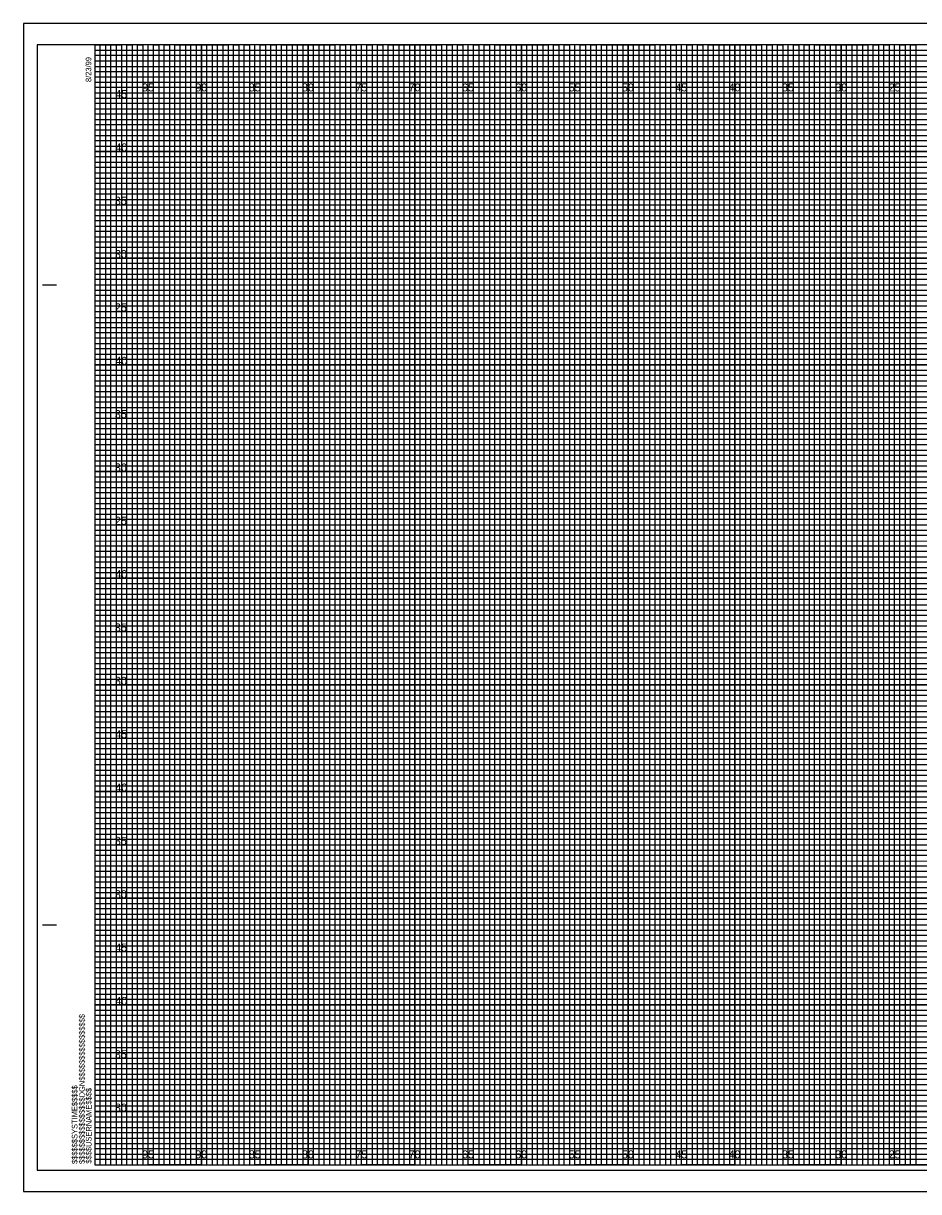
# Model space of a CAD drawing. Extents: x -7 to 162, y 107 to 217.
# Drawn here: x -6.7 to 77.2, y 107.5 to 217 of the extents above; entities that cross this region are included whole.
import ezdxf

# ---------------------------------------------------------------- set-up
doc = ezdxf.new("R2010")
doc.units = 0
for name, color, linetype in [('Exist Cross Section Cell', 7, 'Continuous'), ('Exist XS Center Line Elevation Label', 7, 'Continuous'), ('Exist XS Ground Line', 7, 'Continuous'), ('Prop CMT Pvmt Course 1', 7, 'Continuous'), ('Prop CMT Pvmt Course 2', 7, 'Continuous'), ('Prop CMT Pvmt Course 3', 7, 'Continuous'), ('Prop CMT Shld Paved Course 1', 7, 'Continuous'), ('Prop CMT Shld Paved Course 3', 7, 'Continuous'), ('Prop CMT Slope Grass', 7, 'Continuous'), ('Prop CMT Subgrade Earthwork', 7, 'Continuous'), ('Scratch_Level_0', 7, 'Continuous')]:
    doc.layers.add(name, color=color, linetype=linetype)

msp = doc.modelspace()

# ---------------------------------------------------------------- linework, layer by layer
at = {"layer": 'Exist XS Center Line Elevation Label'}
for points in [[(0, 215), (2.5, 215), (2.5, 110), (7.5, 110), (7.5, 215), (12.5, 215), (12.5, 110), (17.5, 110), (17.5, 215), (22.5, 215), (22.5, 110), (27.5, 110), (27.5, 215), (32.5, 215), (32.5, 110), (37.5, 110), (37.5, 215), (42.5, 215), (42.5, 110), (47.5, 110), (47.5, 215), (52.5, 215), (52.5, 110), (57.5, 110), (57.5, 215), (62.5, 215), (62.5, 110), (67.5, 110), (67.5, 215), (72.5, 215), (72.5, 110), (77.5, 110)], [(0, 212.5), (137.5, 212.5)], [(0, 202.5), (160, 202.5), (160, 207.5), (0, 207.5)], [(0, 192.5), (160, 192.5), (160, 197.5), (0, 197.5)], [(0, 182.5), (160, 182.5), (160, 187.5), (0, 187.5)], [(0, 172.5), (160, 172.5), (160, 177.5), (0, 177.5)], [(0, 162.5), (160, 162.5), (160, 167.5), (0, 167.5)], [(0, 152.5), (160, 152.5), (160, 157.5), (0, 157.5)], [(0, 142.5), (160, 142.5), (160, 147.5), (0, 147.5)], [(0, 132.5), (160, 132.5), (160, 137.5), (0, 137.5)], [(0, 122.5), (160, 122.5), (160, 127.5), (0, 127.5)], [(0, 112.5), (160, 112.5), (160, 117.5), (0, 117.5)]]:
    msp.add_lwpolyline(points, dxfattribs=at)
at = {"layer": 'Exist XS Ground Line'}
for p, q in [((5, 215), (0, 215)), ((5, 110), (5, 215)), ((15, 215), (10, 215)), ((10, 215), (10, 110)), ((15, 110), (15, 215)), ((25, 215), (20, 215)), ((20, 215), (20, 110)), ((25, 110), (25, 215)), ((35, 215), (30, 215)), ((30, 215), (30, 110)), ((35, 110), (35, 215)), ((45, 215), (40, 215)), ((40, 215), (40, 110)), ((45, 110), (45, 215)), ((55, 215), (50, 215)), ((50, 215), (50, 110)), ((55, 110), (55, 215)), ((65, 215), (60, 215)), ((60, 215), (60, 110)), ((65, 110), (65, 215)), ((75, 215), (70, 215)), ((70, 215), (70, 110)), ((75, 110), (75, 215)), ((10, 110), (5, 110)), ((20, 110), (15, 110)), ((30, 110), (25, 110)), ((40, 110), (35, 110)), ((50, 110), (45, 110)), ((60, 110), (55, 110)), ((70, 110), (65, 110)), ((80, 110), (75, 110))]:
    msp.add_line(p, q, dxfattribs=at)
for points in [[(0, 210), (160, 210), (160, 205), (0, 205)], [(0, 200), (160, 200), (160, 195), (0, 195)], [(0, 190), (160, 190), (160, 185), (0, 185)], [(0, 180), (160, 180), (160, 175), (0, 175)], [(0, 170), (160, 170), (160, 165), (0, 165)], [(0, 160), (160, 160), (160, 155), (0, 155)], [(0, 150), (160, 150), (160, 145), (0, 145)], [(0, 140), (160, 140), (160, 135), (0, 135)], [(0, 130), (160, 130), (160, 125), (0, 125)], [(0, 120), (160, 120), (160, 115), (0, 115)]]:
    msp.add_lwpolyline(points, dxfattribs=at)
at = {"layer": 'Prop CMT Pvmt Course 1'}
msp.add_lwpolyline([(-5.4, 109.5), (161.2, 109.5), (161.2, 215), (-5.4, 215)], close=True, dxfattribs=at)
at = {"layer": 'Prop CMT Pvmt Course 2'}
for p, q in [((5, 110), (5, 215)), ((10, 110), (10, 215)), ((15, 110), (15, 215)), ((20, 110), (20, 215)), ((25, 110), (25, 215)), ((30, 110), (30, 215)), ((35, 110), (35, 215)), ((40, 110), (40, 215)), ((45, 110), (45, 215)), ((50, 110), (50, 215)), ((55, 110), (55, 215)), ((60, 110), (60, 215)), ((65, 110), (65, 215)), ((70, 110), (70, 215)), ((75, 110), (75, 215)), ((0, 210), (160, 210)), ((0, 205), (160, 205)), ((0, 200), (160, 200)), ((0, 195), (160, 195)), ((0, 190), (160, 190)), ((0, 185), (160, 185)), ((0, 180), (160, 180)), ((0, 175), (160, 175)), ((0, 170), (160, 170)), ((0, 165), (160, 165)), ((0, 160), (160, 160)), ((0, 155), (160, 155)), ((0, 150), (160, 150)), ((0, 145), (160, 145)), ((0, 140), (160, 140)), ((0, 135), (160, 135)), ((0, 130), (160, 130)), ((0, 125), (160, 125)), ((0, 120), (160, 120)), ((0, 115), (160, 115))]:
    msp.add_line(p, q, dxfattribs=at)
at = {"layer": 'Prop CMT Pvmt Course 3'}
for p, q in [((161.65, 217), (-6.7, 217)), ((-6.7, 217), (-6.7, 107.5)), ((-6.7, 107.5), (161.65, 107.5))]:
    msp.add_line(p, q, dxfattribs=at)
at = {"layer": 'Prop CMT Shld Paved Course 1'}
for points in [[(0, 110), (0.5, 110), (0.5, 215), (1, 215), (1, 110)], [(1, 110), (1.5, 110), (1.5, 215), (2, 215), (2, 110)], [(2.5, 110), (3, 110), (3, 215), (3.5, 215), (3.5, 110)], [(3.5, 110), (4, 110), (4, 215), (4.5, 215), (4.5, 110)], [(5, 110), (5.5, 110), (5.5, 215), (6, 215), (6, 110)], [(6, 110), (6.5, 110), (6.5, 215), (7, 215), (7, 110)], [(7.5, 110), (8, 110), (8, 215), (8.5, 215), (8.5, 110)], [(8.5, 110), (9, 110), (9, 215), (9.5, 215), (9.5, 110)], [(10, 110), (10.5, 110), (10.5, 215), (11, 215), (11, 110)], [(11, 110), (11.5, 110), (11.5, 215), (12, 215), (12, 110)], [(12.5, 110), (13, 110), (13, 215), (13.5, 215), (13.5, 110)], [(13.5, 110), (14, 110), (14, 215), (14.5, 215), (14.5, 110)], [(15, 110), (15.5, 110), (15.5, 215), (16, 215), (16, 110)], [(16, 110), (16.5, 110), (16.5, 215), (17, 215), (17, 110)], [(17.5, 110), (18, 110), (18, 215), (18.5, 215), (18.5, 110)], [(18.5, 110), (19, 110), (19, 215), (19.5, 215), (19.5, 110)], [(20, 110), (20.5, 110), (20.5, 215), (21, 215), (21, 110)], [(21, 110), (21.5, 110), (21.5, 215), (22, 215), (22, 110)], [(22.5, 110), (23, 110), (23, 215), (23.5, 215), (23.5, 110)], [(23.5, 110), (24, 110), (24, 215), (24.5, 215), (24.5, 110)], [(25, 110), (25.5, 110), (25.5, 215), (26, 215), (26, 110)], [(26, 110), (26.5, 110), (26.5, 215), (27, 215), (27, 110)], [(27.5, 110), (28, 110), (28, 215), (28.5, 215), (28.5, 110)], [(28.5, 110), (29, 110), (29, 215), (29.5, 215), (29.5, 110)], [(30, 110), (30.5, 110), (30.5, 215), (31, 215), (31, 110)], [(31, 110), (31.5, 110), (31.5, 215), (32, 215), (32, 110)], [(32.5, 110), (33, 110), (33, 215), (33.5, 215), (33.5, 110)], [(33.5, 110), (34, 110), (34, 215), (34.5, 215), (34.5, 110)], [(35, 110), (35.5, 110), (35.5, 215), (36, 215), (36, 110)], [(36, 110), (36.5, 110), (36.5, 215), (37, 215), (37, 110)], [(37.5, 110), (38, 110), (38, 215), (38.5, 215), (38.5, 110)], [(38.5, 110), (39, 110), (39, 215), (39.5, 215), (39.5, 110)], [(40, 110), (40.5, 110), (40.5, 215), (41, 215), (41, 110)], [(41, 110), (41.5, 110), (41.5, 215), (42, 215), (42, 110)], [(42.5, 110), (43, 110), (43, 215), (43.5, 215), (43.5, 110)], [(43.5, 110), (44, 110), (44, 215), (44.5, 215), (44.5, 110)], [(45, 110), (45.5, 110), (45.5, 215), (46, 215), (46, 110)], [(46, 110), (46.5, 110), (46.5, 215), (47, 215), (47, 110)], [(47.5, 110), (48, 110), (48, 215), (48.5, 215), (48.5, 110)], [(48.5, 110), (49, 110), (49, 215), (49.5, 215), (49.5, 110)], [(50, 110), (50.5, 110), (50.5, 215), (51, 215), (51, 110)], [(51, 110), (51.5, 110), (51.5, 215), (52, 215), (52, 110)], [(52.5, 110), (53, 110), (53, 215), (53.5, 215), (53.5, 110)], [(53.5, 110), (54, 110), (54, 215), (54.5, 215), (54.5, 110)], [(55, 110), (55.5, 110), (55.5, 215), (56, 215), (56, 110)], [(56, 110), (56.5, 110), (56.5, 215), (57, 215), (57, 110)], [(57.5, 110), (58, 110), (58, 215), (58.5, 215), (58.5, 110)], [(58.5, 110), (59, 110), (59, 215), (59.5, 215), (59.5, 110)], [(60, 110), (60.5, 110), (60.5, 215), (61, 215), (61, 110)], [(61, 110), (61.5, 110), (61.5, 215), (62, 215), (62, 110)], [(62.5, 110), (63, 110), (63, 215), (63.5, 215), (63.5, 110)], [(63.5, 110), (64, 110), (64, 215), (64.5, 215), (64.5, 110)], [(65, 110), (65.5, 110), (65.5, 215), (66, 215), (66, 110)], [(66, 110), (66.5, 110), (66.5, 215), (67, 215), (67, 110)], [(67.5, 110), (68, 110), (68, 215), (68.5, 215), (68.5, 110)], [(68.5, 110), (69, 110), (69, 215), (69.5, 215), (69.5, 110)], [(70, 110), (70.5, 110), (70.5, 215), (71, 215), (71, 110)], [(71, 110), (71.5, 110), (71.5, 215), (72, 215), (72, 110)], [(72.5, 110), (73, 110), (73, 215), (73.5, 215), (73.5, 110)], [(73.5, 110), (74, 110), (74, 215), (74.5, 215), (74.5, 110)], [(75, 110), (75.5, 110), (75.5, 215), (76, 215), (76, 110)], [(76, 110), (76.5, 110), (76.5, 215), (77, 215), (77, 110)]]:
    msp.add_lwpolyline(points, dxfattribs=at)
at = {"layer": 'Prop CMT Shld Paved Course 3'}
msp.add_lwpolyline([(-6.7, 107.5), (161.65, 107.5), (161.65, 217), (-6.7, 217)], close=True, dxfattribs=at)
at = {"layer": 'Prop CMT Slope Grass'}
for p, q in [((-4.9, 192.5), (-3.65, 192.5)), ((-4.85, 192.5), (-3.6, 192.5)), ((-4.9, 132.5), (-3.65, 132.5)), ((-4.85, 132.5), (-3.6, 132.5)), ((0, 110), (0, 110)), ((0, 110), (0, 110)), ((0, 110), (0, 110)), ((0, 110), (0, 110)), ((0, 110), (0, 110)), ((0, 110), (0, 110)), ((0, 110), (0, 110))]:
    msp.add_line(p, q, dxfattribs=at)
msp.add_lwpolyline([(160, 215), (0, 215), (0, 110), (160, 110)], close=True, dxfattribs=at)
at = {"layer": 'Scratch_Level_0'}
for p, q in [((0, 214.5), (130, 214.5)), ((130, 213.99), (0, 213.99)), ((0, 213.99), (0, 213.5)), ((0, 213.5), (130, 213.5)), ((130, 212.94), (0, 212.94)), ((0, 212.94), (0, 212)), ((0, 212), (160, 212))]:
    msp.add_line(p, q, dxfattribs=at)
for points in [[(0, 211.5), (135, 211.5), (160, 211.5), (160, 211), (0, 211)], [(0, 210.5), (160, 210.5), (160, 209.5), (0, 209.5)], [(0, 209), (160, 209), (160, 208.5), (0, 208.49)], [(0, 208), (160, 208), (160, 207), (0, 207)], [(0, 206.5), (160, 206.5), (160, 206), (0, 206)], [(0, 205.5), (160, 205.5), (160, 204.5), (0, 204.5)], [(0, 204), (160, 204), (160, 203.5), (0, 203.5)], [(0, 203), (160, 203), (160, 202), (0, 202)], [(0, 201.5), (160, 201.5), (160, 201), (0, 201)], [(0, 200.5), (160, 200.5), (160, 199.5), (0, 199.5)], [(0, 199), (160, 199), (160, 198.5), (0, 198.5)], [(0, 198), (160, 198), (160, 196.97), (160, 196.5), (160, 196), (0, 196)], [(0, 197), (160, 197), (160, 196.5), (0, 196.5)], [(0, 195.5), (160, 195.5), (160, 194.5), (0, 194.52)], [(0, 194.52), (160, 194.5), (160, 194), (0, 194)], [(0, 193.5), (160, 193.5), (160, 193), (0, 193)], [(0, 192), (160, 192), (160, 191.5), (0, 191.5)], [(0, 191), (160, 191), (160, 190.5), (0, 190.5)], [(-0.04, 189.44), (160, 189.44), (160, 188.94), (-0.04, 188.94)], [(0, 188.5), (160, 188.5), (160, 188), (0, 188)], [(0, 187), (160, 187), (160, 186.5), (0, 186.5)], [(0, 186), (160, 186), (160, 185.5), (0, 185.5)], [(0, 184.5), (160, 184.5), (160, 184), (0, 184)], [(0, 183.5), (160, 183.5), (160, 183), (0, 183)], [(0, 182), (160, 182), (160, 181.5), (0, 181.5)], [(0, 181), (160, 181), (160, 180.5), (0, 180.5)], [(0, 179.5), (160, 179.5), (160, 178.99), (0, 179)], [(0, 178.5), (160, 178.5), (160, 178), (0, 178)], [(0, 177), (160, 177), (160, 176.5), (0, 176.5)], [(0, 176), (160, 176), (160, 175.5), (0, 175.5)], [(0, 174.5), (160, 174.5), (160, 174), (0, 174)], [(0, 173.5), (160, 173.5), (160, 173), (0, 173)], [(0, 172), (160, 172), (160, 171.5), (0, 171.5)], [(0, 171), (160, 171), (160, 170.5), (0, 170.5)], [(0, 169.5), (160, 169.5), (160, 169), (0, 169)], [(0, 168.5), (160.03, 168.46), (160, 168), (0, 168)], [(0, 167), (160, 167), (160, 166.5), (0, 166.5)], [(0, 166), (160, 166), (160, 165.5), (0, 165.5)], [(0, 164.5), (160, 164.5), (160, 164), (0, 164)], [(0, 163.5), (160, 163.5), (160, 163), (0, 163)], [(0, 162), (160, 162), (160, 161.5), (0, 161.5)], [(0, 161), (160, 161), (160, 160.5), (0, 160.5)], [(0, 159.5), (160, 159.5), (160, 159), (0, 159)], [(0, 158.5), (160, 158.5), (160, 158), (0, 158)], [(0, 157), (160, 157), (160, 156.5), (0, 156.5)], [(0, 156), (160, 156), (160, 155.5), (0, 155.5)], [(0, 154.5), (160, 154.5), (160, 154), (0, 154)], [(0, 153.5), (160, 153.5), (160, 153), (0, 153)], [(0, 152), (160, 152), (160, 151.5), (0, 151.5)], [(0, 151), (160, 151), (160, 150.5), (0, 150.5)], [(0, 149.5), (160, 149.5), (160, 148.99), (0, 149)], [(0, 148.5), (160, 148.5), (160, 148), (0, 148)], [(0, 147), (160, 147), (160, 146.5), (0, 146.5)], [(0, 146), (160, 146), (160, 145.5), (0, 145.5)], [(0, 144.5), (160, 144.5), (160, 144), (0, 144)], [(0, 143.5), (160, 143.5), (160, 143), (0, 143)], [(0, 142), (160, 142), (160, 141.5), (0, 141.5)], [(0, 141), (160, 141), (160, 140.5), (0, 140.5)], [(0, 139.5), (160, 139.5), (160, 139), (0, 139)], [(0, 138.5), (160.03, 138.46), (160, 138), (0, 138)], [(0, 137), (160, 137), (160, 136.5), (0, 136.5)], [(0, 136), (160, 136), (160, 135.5), (0, 135.5)], [(0, 134.5), (160, 134.5), (160, 134), (0, 134)], [(0, 133.5), (160, 133.5), (160, 133), (0, 133)], [(0, 132), (160, 132), (160, 131.5), (0, 131.5)], [(0, 131), (160, 131), (160, 130.5), (0, 130.5)], [(0, 129.5), (160, 129.5), (160, 129), (0, 129)], [(0, 128.5), (160, 128.5), (160, 128), (0, 128)], [(0, 127), (160, 127), (160, 126.5), (0, 126.5)], [(0, 126), (160, 126), (160, 125.5), (0, 125.5)], [(0, 124.5), (160, 124.5), (160, 124), (0, 124)], [(0, 123.5), (160, 123.5), (160, 123), (0, 123)], [(0, 122), (160, 122), (160, 121.5), (0, 121.5)], [(0, 121), (160, 121), (160, 120.5), (0, 120.5)], [(0, 119.5), (160, 119.5), (160, 119), (0, 119)], [(0, 118.5), (160, 118.5), (160, 118), (0, 118)], [(0, 117), (160, 117), (160, 116.5), (0, 116.5)], [(0, 116), (160, 116), (160, 115.5), (0, 115.5)], [(0, 114.5), (160, 114.5), (160, 114), (0, 114)], [(0, 113.5), (160, 113.5), (160, 113), (0, 113)], [(0, 112), (160, 112), (160, 111.5), (0, 111.5)], [(0, 111), (160, 111), (160, 110.5), (0, 110.5)]]:
    msp.add_lwpolyline(points, dxfattribs=at)

# ---------------------------------------------------------------- texts
at = {"layer": 'Exist Cross Section Cell'}
for s, p in [('95', (4.44, 210.62)), ('90', (9.43, 210.62)), ('85', (14.44, 210.62)), ('80', (19.43, 210.62)), ('75', (24.44, 210.62)), ('70', (29.43, 210.62)), ('65', (34.44, 210.62)), ('60', (39.43, 210.62)), ('55', (44.44, 210.62)), ('50', (49.43, 210.62)), ('45', (54.44, 210.62)), ('40', (59.43, 210.62)), ('35', (64.44, 210.62)), ('30', (69.43, 210.62)), ('25', (74.44, 210.62)), ('95', (4.44, 110.62)), ('90', (9.43, 110.62)), ('85', (14.44, 110.62)), ('80', (19.43, 110.62)), ('75', (24.44, 110.62)), ('70', (29.43, 110.62)), ('65', (34.44, 110.62)), ('60', (39.43, 110.62)), ('55', (44.44, 110.62)), ('50', (49.43, 110.62)), ('45', (54.44, 110.62)), ('40', (59.43, 110.62)), ('35', (64.44, 110.62)), ('30', (69.43, 110.62)), ('25', (74.44, 110.62))]:
    msp.add_text(s, height=0.75, dxfattribs=at).set_placement(p)
at = {"layer": 'Prop CMT Slope Grass'}
for s, p in [('8/23/99', (-0.33, 211.5)), ('$$$$$$$$$$$$$$$$DGN$$$$$$$$$$$$$$$$', (-0.94, 110.09)), ('$$$$$$SYSTIME$$$$$', (-1.63, 110.09)), ('$$$$USERNAME$$$$', (-0.31, 110.12))]:
    msp.add_text(s, height=0.525, rotation=90, dxfattribs=at).set_placement(p)
at = {"layer": 'Prop CMT Subgrade Earthwork'}
for s, p in [('45', (1.92, 210)), ('40', (1.93, 205)), ('35', (1.88, 200)), ('30', (1.89, 195)), ('25', (1.89, 190)), ('40', (1.93, 185)), ('35', (1.88, 180)), ('30', (1.89, 175)), ('25', (1.89, 170)), ('40', (1.93, 165)), ('35', (1.88, 160)), ('30', (1.89, 155)), ('45', (1.92, 150)), ('40', (1.93, 145)), ('35', (1.88, 140)), ('30', (1.89, 135)), ('45', (1.92, 130)), ('40', (1.93, 125)), ('35', (1.88, 120)), ('30', (1.89, 115))]:
    msp.add_text(s, height=0.75, dxfattribs=at).set_placement(p)

doc.saveas('drawing.dxf')
